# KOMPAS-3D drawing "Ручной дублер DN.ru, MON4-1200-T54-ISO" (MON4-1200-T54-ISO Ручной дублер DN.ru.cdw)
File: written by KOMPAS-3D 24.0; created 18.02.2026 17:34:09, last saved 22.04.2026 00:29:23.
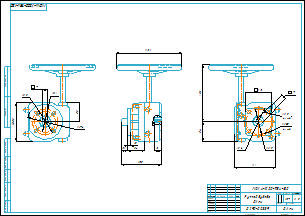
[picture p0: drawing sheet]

Document properties: Автор: R2D2; Форматы листов документа: A2; Полное имя файла: MON4-1200-T54-ISO Ручной дублер DN.ru.m3d; Масса: 13.7; Наименование: Ручной дублер DN.ru; Количество листов документа: 1; Примечание: D290-00339

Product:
- Part/product: Ручной дублер DN.ru  | designation MON4-1200-T54-ISO
    Масса: 13.7
    Раздел спецификации: Прочие изделия
    Примечание: D290-00339

Views: Вид 1, Спереди, Проекционный вид 2, Местный разрез 1, Проекционный вид 3
Referenced files in E:\Работа\Зайцев\Аксессуары для пневмоприводов\Ручной дублер DN.ru\MON4-1200-T54-ISO Ручной дублер DN.ru\: MON4-1200-T54-ISO Ручной дублер DN.ru.m3d
Referenced files in E:\Работа\Зайцев\Для компаса\: чертеж DN.ru А3.cdt
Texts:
  MON4-1200-T54-ISO
  чертеж DN.ru А3.cdt
  Ручной дублер
  Ручной дублер DN.ru
  MON4-1200-T54-ISO Ручной дублер DN.ru
Dimensions and other numbers on the sheet: 0; 3; 2; 4; 188,5; 174; 125; 102; 27; 93; 195; 32; 30; 15; 84; 320; 129; 280; 94; 202; 140; 12,5; 4 отв.; 16,5; 1:2,5; 1; 13,7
